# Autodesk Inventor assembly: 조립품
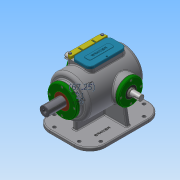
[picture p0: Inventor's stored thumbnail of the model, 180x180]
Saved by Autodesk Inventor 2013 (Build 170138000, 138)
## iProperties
Created: 2019-10
Part Number: 조립품
Document SubType Name: Assembly
Designer: Administrator
Author: Administrator
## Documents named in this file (17)
- C:\Users\Administrator\Desktop\391004V1032\조립품.iam
- C:\Users\Administrator\Desktop\391004V1032\본체.ipt
- C:\Users\Administrator\Desktop\391004V1032\개스킷 A.ipt
- C:\Users\Administrator\Desktop\391004V1032\개스킷 B.ipt
- C:\Users\Administrator\Desktop\391004V1032\고정플레이트.ipt
- C:\Users\Administrator\Desktop\391004V1032\베어링 6205.ipt
- 베어링 6205.ipt
- C:\Users\Administrator\Desktop\391004V1032\볼트 M4x0.7.ipt
- C:\Users\Administrator\Desktop\391004V1032\부시.ipt
- C:\Users\Administrator\Desktop\391004V1032\상부커버.ipt
- C:\Users\Administrator\Desktop\391004V1032\슬라이드 커버.ipt
- C:\Users\Administrator\Desktop\391004V1032\슬라이드.ipt
- C:\Users\Administrator\Desktop\391004V1032\오일 실 25 38 8.ipt
- C:\Users\Administrator\Desktop\391004V1032\육각머리볼트 M4.ipt
- C:\Users\Administrator\Desktop\391004V1032\축 커버.ipt
- C:\Users\Administrator\Desktop\391004V1032\편심축.ipt
- C:\Users\Administrator\Desktop\391004V1032\스프링.ipt
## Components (16 placed, 4 different names)
1. 개스킷 A:1
2. 개스킷 B:1
3. 고정플레이트:1 — 플러쉬:1
4. M4x0.7:1
5. 개스킷 B:2
6. M4x0.7:2
7. M4x0.7:3
8. M4x0.7:4
9. M4x0.7:5
10. M4x0.7:6
11. M4x0.7:7
12. M4x0.7:8
13. M4x0.7:9
14. M4x0.7:10
15. M4x0.7:11
16. M4x0.7:12
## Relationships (1: Flush 1)
- 플러쉬:1 [Flush]: 고정플레이트:1
